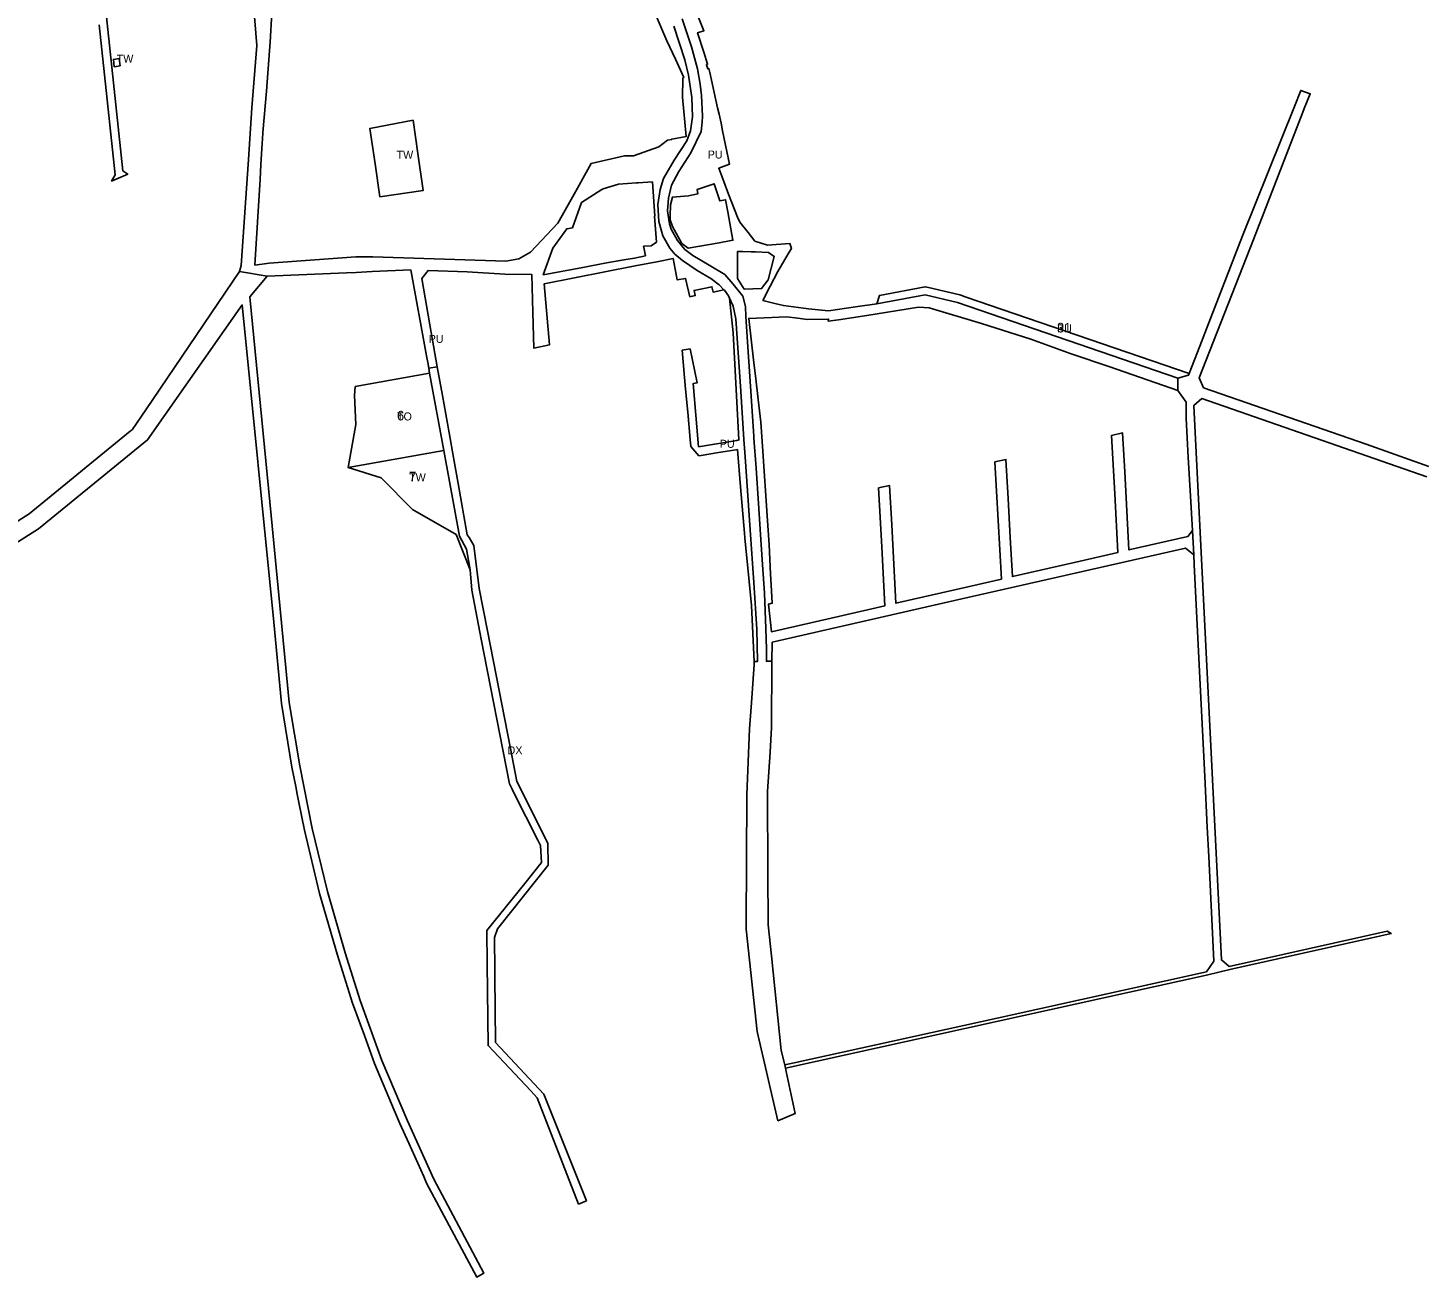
# Model space of a CAD drawing. Extents: x -521882 to -518995, y -1142400 to -1140153.
# Drawn here: x -520739 to -519867, y -1141816 to -1141035 of the extents above; entities that cross this region are included whole.
import ezdxf

# ---------------------------------------------------------------- set-up
doc = ezdxf.new("R2010")
doc.units = 0
for name, color, linetype in [('90320013', 7, 'Continuous'), ('90370013', 7, 'Continuous'), ('90390013', 7, 'Continuous'), ('90390023', 7, 'Continuous'), ('90430023', 7, 'Continuous'), ('90450013', 7, 'Continuous'), ('90450023', 7, 'Continuous'), ('ID_navrh', 7, 'Continuous')]:
    doc.layers.add(name, color=color, linetype=linetype)

msp = doc.modelspace()

# ---------------------------------------------------------------- linework, layer by layer
at = {"layer": '90320013'}
msp.add_lwpolyline([(-520330.66, -1141029.65), (-520324.76, -1141047.17), (-520321.07, -1141060.89), (-520319.27, -1141070.53), (-520318.44, -1141077.73), (-520317.76, -1141090.48), (-520318.04, -1141094.37), (-520318.78, -1141100.08), (-520325.12, -1141113.35), (-520332.74, -1141125.19), (-520337.15, -1141133.73), (-520339.09, -1141141.84), (-520339.64, -1141149.76), (-520338.41, -1141157.75), (-520337.34, -1141161.13), (-520333.5, -1141168.21), (-520328.85, -1141173.77), (-520323.9, -1141177.63), (-520313.7, -1141183.68), (-520304, -1141189.53), (-520298.66, -1141195.42), (-520292.63, -1141202.98), (-520290.93, -1141209.43), (-520290.72, -1141215.76), (-520289.28, -1141237.74), (-520287.43, -1141265.4), (-520285.78, -1141290.4), (-520285.69, -1141291.6), (-520284.36, -1141310.52), (-520282.86, -1141332.45), (-520281.66, -1141351.81), (-520280.36, -1141370.5), (-520279.11, -1141388.58), (-520278.27, -1141410.62), (-520277.86, -1141423.4), (-520277.92, -1141430.99), (-520274.48, -1141431.01), (-520274.69, -1141472.35), (-520275.67, -1141487.93), (-520277.2, -1141512.43), (-520277.03, -1141563.71), (-520276.93, -1141594.74), (-520276.82, -1141595.78), (-520274.84, -1141614.95), (-520268.73, -1141674.23), (-520266.52, -1141683.24), (-520266.08, -1141685.14), (-520265.6, -1141687.35), (-520259.91, -1141713.53), (-520270.75, -1141718.04), (-520283.67, -1141662.22), (-520290.53, -1141598.43), (-520290.52, -1141595.71), (-520290.19, -1141514.57), (-520288.42, -1141473.23), (-520287.25, -1141456.97), (-520285.53, -1141433.12), (-520285.62, -1141431.18), (-520283.46, -1141431.12), (-520283.95, -1141411.07), (-520285.88, -1141381.79), (-520288.07, -1141348.91), (-520291.26, -1141303.35), (-520291.98, -1141292.42), (-520293.97, -1141262.32), (-520297.11, -1141217.05), (-520298.67, -1141209.18), (-520300.95, -1141204.15), (-520301.55, -1141202.8), (-520304.21, -1141199.32), (-520304.49, -1141199.02), (-520307.43, -1141195.9), (-520312.59, -1141191.95), (-520321.21, -1141186.85), (-520330.27, -1141180.78), (-520335.19, -1141176.69), (-520338.22, -1141172.95), (-520342.68, -1141165.24), (-520343.69, -1141161.58), (-520345.14, -1141156.25), (-520345.84, -1141145.82), (-520344.38, -1141136.25), (-520342.14, -1141129.51), (-520335.59, -1141118), (-520327.56, -1141105.89), (-520325.35, -1141099.6), (-520324.16, -1141090.88), (-520324.51, -1141078.81), (-520326.63, -1141065), (-520328.86, -1141055.37), (-520335.75, -1141034.28)], dxfattribs=at)
at = {"layer": '90370013'}
for points in [[(-520699.09, -1140943.92), (-520679.92, -1141124.76), (-520676.95, -1141126.77), (-520686.99, -1141131.09), (-520684.73, -1141127.15), (-520694.75, -1141033.39)], [(-519865.42, -1141315.8), (-520005.98, -1141266.96), (-520010.89, -1141271.2), (-520005.29, -1141383.92), (-519993.67, -1141617.6), (-519988.83, -1141621.62), (-519890.16, -1141599.67), (-519887.54, -1141601.15), (-519894.12, -1141602.61), (-519988.36, -1141623.57), (-520003.05, -1141627.05), (-520133.25, -1141655.87), (-520266.08, -1141685.14), (-520266.52, -1141683.24), (-520260.66, -1141681.95), (-520133.69, -1141653.91), (-520003.08, -1141624.98), (-519998.35, -1141618.37), (-520001.59, -1141552.99), (-520002.49, -1141534.74), (-520004.05, -1141503.1), (-520007.71, -1141429.14), (-520010.61, -1141370.65), (-520010.91, -1141364.55), (-520011.78, -1141349.43), (-520013.01, -1141327.96), (-520014.41, -1141303.65), (-520015.8, -1141279.3), (-520015.63, -1141269.2), (-520020.82, -1141261.97), (-520020.92, -1141254.2), (-520014.17, -1141252.24), (-520013.82, -1141251.35), (-520007.17, -1141234.15), (-520002.99, -1141223.35), (-519980.55, -1141165.39), (-519948.1, -1141084.44), (-519944.08, -1141074.41), (-519938.17, -1141076.59), (-519941.9, -1141085.78), (-519942.77, -1141088.03), (-519973.57, -1141167.53), (-520007.53, -1141254.06), (-520004.78, -1141260.17), (-519903.26, -1141295.46), (-519864.09, -1141309.46)], [(-520773.04, -1141360.9), (-520738.6, -1141338.95), (-520675.31, -1141287.41), (-520674.18, -1141286.49), (-520665.65, -1141273.94), (-520607.02, -1141187.64), (-520589.77, -1141190.43), (-520600.66, -1141203.4), (-520587.35, -1141340.09), (-520576, -1141456.7), (-520569.46, -1141496.36), (-520561.68, -1141535.49), (-520552.2, -1141574.91), (-520541.05, -1141613.27), (-520531.72, -1141643.02), (-520518.1, -1141680.34), (-520502.23, -1141718.09), (-520485.78, -1141754.61), (-520454.47, -1141813.35), (-520454.91, -1141813.57), (-520458.87, -1141815.72), (-520490.19, -1141756.96), (-520491.98, -1141752.99), (-520501.37, -1141732.13), (-520506.95, -1141719.75), (-520510.4, -1141711.55), (-520522.71, -1141682.28), (-520528.04, -1141667.68), (-520529.1, -1141664.77), (-520536.49, -1141644.52), (-520545.85, -1141614.67), (-520557.06, -1141576.08), (-520566.58, -1141536.47), (-520569.98, -1141519.36), (-520571.03, -1141514.08), (-520572, -1141509.22), (-520574.39, -1141497.17), (-520580.93, -1141457.51), (-520585.72, -1141406.64), (-520605.35, -1141208.42), (-520664.52, -1141292.81), (-520732.72, -1141348.25), (-520768.7, -1141371.01)]]:
    msp.add_lwpolyline(points, dxfattribs=at)
msp.add_lwpolyline([(-520390.37, -1141768.15), (-520395.26, -1141770.17), (-520405.02, -1141744.98), (-520421.11, -1141703.69), (-520425.12, -1141699.44), (-520451.86, -1141671.07), (-520452.43, -1141620.06), (-520452.66, -1141599.19), (-520428.95, -1141569.87), (-520418.4, -1141556.83), (-520419, -1141546.21), (-520420.69, -1141542.88), (-520435.68, -1141513.27), (-520436.83, -1141511), (-520438.53, -1141507.64), (-520456.11, -1141417.28), (-520462.06, -1141386.7), (-520463.1, -1141373.93), (-520465.21, -1141361), (-520469.72, -1141352.88), (-520479.49, -1141299.41), (-520488.31, -1141251.1), (-520488.89, -1141247.94), (-520483.58, -1141247.19), (-520480.37, -1141265.08), (-520476.2, -1141288.34), (-520473.45, -1141303.71), (-520470.52, -1141320.08), (-520464.8, -1141352.03), (-520463.71, -1141353.8), (-520460.62, -1141358.83), (-520457.31, -1141385.57), (-520452.14, -1141412.08), (-520437.82, -1141485.59), (-520433.82, -1141506.13), (-520414.56, -1141544.64), (-520414.26, -1141558.37), (-520446.02, -1141598.19), (-520447.82, -1141603.5), (-520447.63, -1141624.46), (-520447.6, -1141627.85), (-520447.22, -1141669.1), (-520417.08, -1141701.53)], close=True, dxfattribs=at)
at = {"layer": '90390013'}
for points in [[(-520681.75, -1141059.18), (-520685.33, -1141059.63), (-520685.9, -1141055.06), (-520682.32, -1141054.61)], [(-520498.69, -1141092.95), (-520495.67, -1141113.78), (-520492.31, -1141136.96), (-520519.42, -1141140.9), (-520522.42, -1141120.25), (-520525.62, -1141098.2)]]:
    msp.add_lwpolyline(points, close=True, dxfattribs=at)
at = {"layer": '90390023'}
msp.add_lwpolyline([(-520479.49, -1141299.41), (-520469.72, -1141352.88), (-520465.21, -1141361), (-520463.1, -1141373.93), (-520471.76, -1141351.9), (-520499.06, -1141336.21), (-520518.61, -1141316.36), (-520539.2, -1141310.09)], close=True, dxfattribs=at)
at = {"layer": '90430023'}
msp.add_lwpolyline([(-520488.31, -1141251.1), (-520479.49, -1141299.41), (-520539.2, -1141310.09), (-520534.35, -1141283.17), (-520535.3, -1141264.93), (-520534.84, -1141259.42)], close=True, dxfattribs=at)
at = {"layer": '90450013'}
for points in [[(-520335.75, -1141034.28), (-520328.86, -1141055.37), (-520326.63, -1141065), (-520324.51, -1141078.81), (-520324.16, -1141090.88), (-520325.35, -1141099.6), (-520327.56, -1141105.89), (-520335.59, -1141118), (-520342.14, -1141129.51), (-520344.38, -1141136.25), (-520345.84, -1141145.82), (-520345.14, -1141156.25), (-520343.69, -1141161.58), (-520342.68, -1141165.24), (-520338.22, -1141172.95), (-520335.19, -1141176.69), (-520330.27, -1141180.78), (-520321.21, -1141186.85), (-520312.59, -1141191.95), (-520307.43, -1141195.9), (-520304.49, -1141199.02), (-520311.28, -1141200.4), (-520312, -1141197.1), (-520323.1, -1141199.37), (-520322.39, -1141202.63), (-520325.76, -1141203.31), (-520328.4, -1141191.92), (-520333.6, -1141192.88), (-520336.24, -1141179.42), (-520346.46, -1141181.44), (-520359.99, -1141184.11), (-520416.76, -1141195.21), (-520413.51, -1141233.43), (-520423.33, -1141235.38), (-520423.9, -1141213.13), (-520424.53, -1141189.37), (-520441.37, -1141189.15), (-520464.88, -1141187.85), (-520489.31, -1141186.91), (-520493.12, -1141191.96), (-520488.14, -1141220.84), (-520483.58, -1141247.19), (-520488.89, -1141247.94), (-520489.54, -1141244.37), (-520490.28, -1141240.29), (-520500.08, -1141186.63), (-520524.27, -1141187.6), (-520534.17, -1141188.18), (-520540.34, -1141188.43), (-520589.77, -1141190.43), (-520607.02, -1141187.64), (-520606.07, -1141183.78), (-520601.54, -1141117.64), (-520599.33, -1141085.41), (-520596.21, -1141046.3), (-520598.37, -1141020.83)], [(-520586.99, -1141025.98), (-520587.85, -1141044.25), (-520588.29, -1141049.68), (-520590.32, -1141074.97), (-520592.43, -1141100.83), (-520592.76, -1141104.85), (-520592.91, -1141107.42), (-520593.72, -1141120.93), (-520594.25, -1141129.86), (-520597.46, -1141183.55), (-520588.63, -1141182.42), (-520534.49, -1141178.34), (-520530.26, -1141178.39), (-520526.48, -1141178.44), (-520523.78, -1141178.47), (-520440.68, -1141181.04), (-520432.59, -1141179.7), (-520425.27, -1141175.41), (-520408.18, -1141157.48), (-520397.97, -1141139.24), (-520387.46, -1141120.02), (-520366.58, -1141115.24), (-520361.02, -1141115.3), (-520345.24, -1141109.63), (-520339.78, -1141105.62), (-520337.04, -1141105.09), (-520337.09, -1141104.85), (-520328.09, -1141103.27), (-520330.35, -1141078.64), (-520330.22, -1141066.74), (-520329.51, -1141066.36), (-520334.74, -1141054.84), (-520340.18, -1141043.47), (-520343.25, -1141036.1), (-520347.88, -1141025.34)], [(-520321.6, -1141025.87), (-520317.01, -1141037.16), (-520320.97, -1141038.48), (-520317.05, -1141050.62), (-520314.7, -1141058.15), (-520315.46, -1141058.39), (-520314.63, -1141061.07), (-520313.88, -1141060.82), (-520313.18, -1141063.23), (-520308.39, -1141085.31), (-520307.52, -1141089.35), (-520306.28, -1141094.87), (-520305.34, -1141099.75), (-520302.64, -1141112.56), (-520300.97, -1141120.47), (-520307.67, -1141123.05), (-520305.82, -1141127.93), (-520301.56, -1141139.26), (-520296.03, -1141153.59), (-520294.54, -1141156.83), (-520289.43, -1141163.17), (-520285.07, -1141168.6), (-520277.22, -1141171.12), (-520271.87, -1141170.72), (-520263.33, -1141170.08), (-520262.34, -1141173.28), (-520263.7, -1141175.46), (-520265.8, -1141179.08), (-520267.83, -1141182.58), (-520270.74, -1141187.55), (-520275.56, -1141196.82), (-520280.13, -1141205.59), (-520272.66, -1141207.5), (-520267.32, -1141208.86), (-520251.72, -1141210.86), (-520239.07, -1141212.2), (-520222.29, -1141209.66), (-520209, -1141207.86), (-520178.85, -1141202.22), (-520158.56, -1141206.98), (-520020.92, -1141254.2), (-520020.82, -1141261.97), (-520063.43, -1141247.22), (-520087.52, -1141238.96), (-520112.81, -1141229.84), (-520143.54, -1141220.12), (-520176.27, -1141210.31), (-520182.91, -1141209.86), (-520215.27, -1141215.02), (-520232.83, -1141217.82), (-520239.26, -1141218.7), (-520239.12, -1141217.25), (-520252.46, -1141217.61), (-520258.35, -1141216.74), (-520265.11, -1141215.87), (-520284.22, -1141216.65), (-520288.93, -1141216.9), (-520285.74, -1141244.64), (-520284.8, -1141252.79), (-520283.12, -1141267.46), (-520281.48, -1141281.72), (-520280.23, -1141299.79), (-520277.43, -1141340.16), (-520276.18, -1141358.36), (-520275.42, -1141376.5), (-520274.78, -1141387.08), (-520274.32, -1141394.81), (-520276.63, -1141395.38), (-520274.78, -1141412.59), (-520230.23, -1141402.41), (-520203.85, -1141396.38), (-520205.86, -1141359.46), (-520207.86, -1141322.8), (-520200.99, -1141321.26), (-520199.66, -1141345.79), (-520198.32, -1141370.3), (-520196.98, -1141394.82), (-520157.5, -1141385.79), (-520131.16, -1141379.76), (-520133.15, -1141343.14), (-520135.15, -1141306.52), (-520128.28, -1141304.98), (-520126.95, -1141329.38), (-520125.62, -1141353.79), (-520124.29, -1141378.19), (-520084.7, -1141369.12), (-520058.3, -1141363.08), (-520060.29, -1141326.5), (-520062.28, -1141289.92), (-520055.42, -1141288.36), (-520054.09, -1141312.76), (-520052.77, -1141337.11), (-520051.44, -1141361.51), (-520014.56, -1141353.06), (-520011.78, -1141349.43), (-520010.91, -1141364.55), (-520016.19, -1141360.33), (-520155.8, -1141392.1), (-520274.28, -1141419.2), (-520274.48, -1141431.01), (-520277.92, -1141430.99), (-520277.86, -1141423.4), (-520278.27, -1141410.62), (-520279.11, -1141388.58), (-520280.36, -1141370.5), (-520281.66, -1141351.81), (-520282.86, -1141332.45), (-520284.36, -1141310.52), (-520285.69, -1141291.6), (-520285.78, -1141290.4), (-520287.43, -1141265.4), (-520289.28, -1141237.74), (-520290.72, -1141215.76), (-520290.93, -1141209.43), (-520292.63, -1141202.98), (-520298.66, -1141195.42), (-520304, -1141189.53), (-520313.7, -1141183.68), (-520323.9, -1141177.63), (-520328.85, -1141173.77), (-520333.5, -1141168.21), (-520337.34, -1141161.13), (-520338.41, -1141157.75), (-520339.64, -1141149.76), (-520339.09, -1141141.84), (-520337.15, -1141133.73), (-520332.74, -1141125.19), (-520325.12, -1141113.35), (-520318.78, -1141100.08), (-520318.04, -1141094.37), (-520317.76, -1141090.48), (-520318.44, -1141077.73), (-520319.27, -1141070.53), (-520321.07, -1141060.89), (-520324.76, -1141047.17), (-520330.66, -1141029.65)]]:
    msp.add_lwpolyline(points, dxfattribs=at)
for points in [[(-520392.71, -1141184.99), (-520378.86, -1141182.41), (-520366.93, -1141180.34), (-520360.34, -1141179.18), (-520353.47, -1141177.71), (-520354.34, -1141173.71), (-520354.71, -1141171.83), (-520349.86, -1141171.48), (-520346.65, -1141169.3), (-520347.81, -1141152.92), (-520347.61, -1141152.91), (-520349.11, -1141131.64), (-520357.95, -1141132.21), (-520359.15, -1141132.28), (-520370.32, -1141133), (-520379.87, -1141135.97), (-520380.82, -1141136.27), (-520393.37, -1141144.49), (-520399.1, -1141160.34), (-520402.63, -1141160.92), (-520411.3, -1141173.03), (-520417.36, -1141189.63)], [(-520337.89, -1141145.94), (-520338.1, -1141152.71), (-520338.08, -1141155.23), (-520336.67, -1141159.38), (-520330.81, -1141170.06), (-520326.87, -1141172.95), (-520319.49, -1141171.67), (-520307.53, -1141169.64), (-520298.87, -1141168.07), (-520302.11, -1141150.23), (-520303.47, -1141142.76), (-520307.07, -1141143.41), (-520310.58, -1141132.78), (-520321.22, -1141136.45), (-520320.69, -1141138.98), (-520326.63, -1141140.31), (-520336.61, -1141141.05)], [(-520292.9, -1141175.16), (-520296.01, -1141175.11), (-520295.98, -1141192.02), (-520291.83, -1141198.59), (-520280.99, -1141198.2), (-520276.81, -1141192.82), (-520273.02, -1141178.12), (-520276.61, -1141175.8), (-520284.8, -1141175.38), (-520287.4, -1141175.25)], [(-520325.59, -1141235.8), (-520321.16, -1141257.11), (-520323.62, -1141257.49), (-520320.29, -1141297.03), (-520296.48, -1141293.05), (-520295.11, -1141292.82), (-520298.61, -1141225.85), (-520300.95, -1141204.15), (-520298.67, -1141209.18), (-520297.11, -1141217.05), (-520293.97, -1141262.32), (-520291.98, -1141292.42), (-520291.26, -1141303.35), (-520288.07, -1141348.91), (-520285.88, -1141381.79), (-520283.95, -1141411.07), (-520283.46, -1141431.12), (-520285.62, -1141431.18), (-520287.2, -1141396.11), (-520288.69, -1141381.19), (-520291.41, -1141353.94), (-520291.7, -1141351.03), (-520294.09, -1141322.02), (-520296, -1141298.82), (-520298.25, -1141299.19), (-520307.88, -1141300.74), (-520318.74, -1141302.49), (-520320.11, -1141302.71), (-520325.09, -1141296.95), (-520325.5, -1141292.44), (-520327.05, -1141275.53), (-520328.39, -1141261.02), (-520330.62, -1141236.74)]]:
    msp.add_lwpolyline(points, close=True, dxfattribs=at)
at = {"layer": '90450023'}
msp.add_lwpolyline([(-520013.82, -1141251.35), (-520014.17, -1141252.24), (-520020.92, -1141254.2), (-520158.56, -1141206.98), (-520178.85, -1141202.22), (-520209, -1141207.86), (-520207.36, -1141202.47), (-520178.73, -1141197.11), (-520176.64, -1141197.6), (-520157.17, -1141202.17), (-520156.44, -1141202.42), (-520153.86, -1141203.31)], close=True, dxfattribs=at)

# ---------------------------------------------------------------- texts
at = {"layer": '90370013'}
msp.add_text('DX', height=5, rotation=360, dxfattribs=at).set_placement((-520439.63, -1141489.14))
at = {"layer": '90390013'}
for p in [(-520683.82, -1141057.12), (-520508.97, -1141117.17)]:
    msp.add_text('TW', height=5, rotation=0, dxfattribs=at).set_placement(p)
at = {"layer": '90390023'}
msp.add_text('TW', height=5, rotation=360, dxfattribs=at).set_placement((-520501.15, -1141318.69))
at = {"layer": '90430023'}
msp.add_text('TO', height=5, rotation=0, dxfattribs=at).set_placement((-520508.7, -1141280.6))
at = {"layer": '90450013'}
for rotation, p in [(360, (-520314.59, -1141117)), (360, (-520488.9, -1141232.16)), (0, (-520307.04, -1141297.71))]:
    msp.add_text('PU', height=5, rotation=rotation, dxfattribs=at).set_placement(p)
at = {"layer": '90450023'}
msp.add_text('PU', height=5, rotation=360, dxfattribs=at).set_placement((-520096.42, -1141225.65))
at = {"layer": 'ID_navrh'}
for s, rotation, p in [('31', 360, (-520096.42, -1141225.65)), ('6', 0, (-520508.7, -1141280.6)), ('7', 0, (-520501.15, -1141318.69))]:
    msp.add_text(s, height=6, rotation=rotation, dxfattribs=at).set_placement(p)

doc.saveas('drawing.dxf')
